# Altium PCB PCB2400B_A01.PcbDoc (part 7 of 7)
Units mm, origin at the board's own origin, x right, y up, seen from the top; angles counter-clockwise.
Board outline 115 x 60 mm, 6 copper layers (Top Layer, Signal Layer 2, Signal Layer 3, Signal Layer 4, Signal Layer 5, Bottom Layer), stack 1.555 mm thick; 382 components, 308 nets, 1384 pads, 1152 vias.
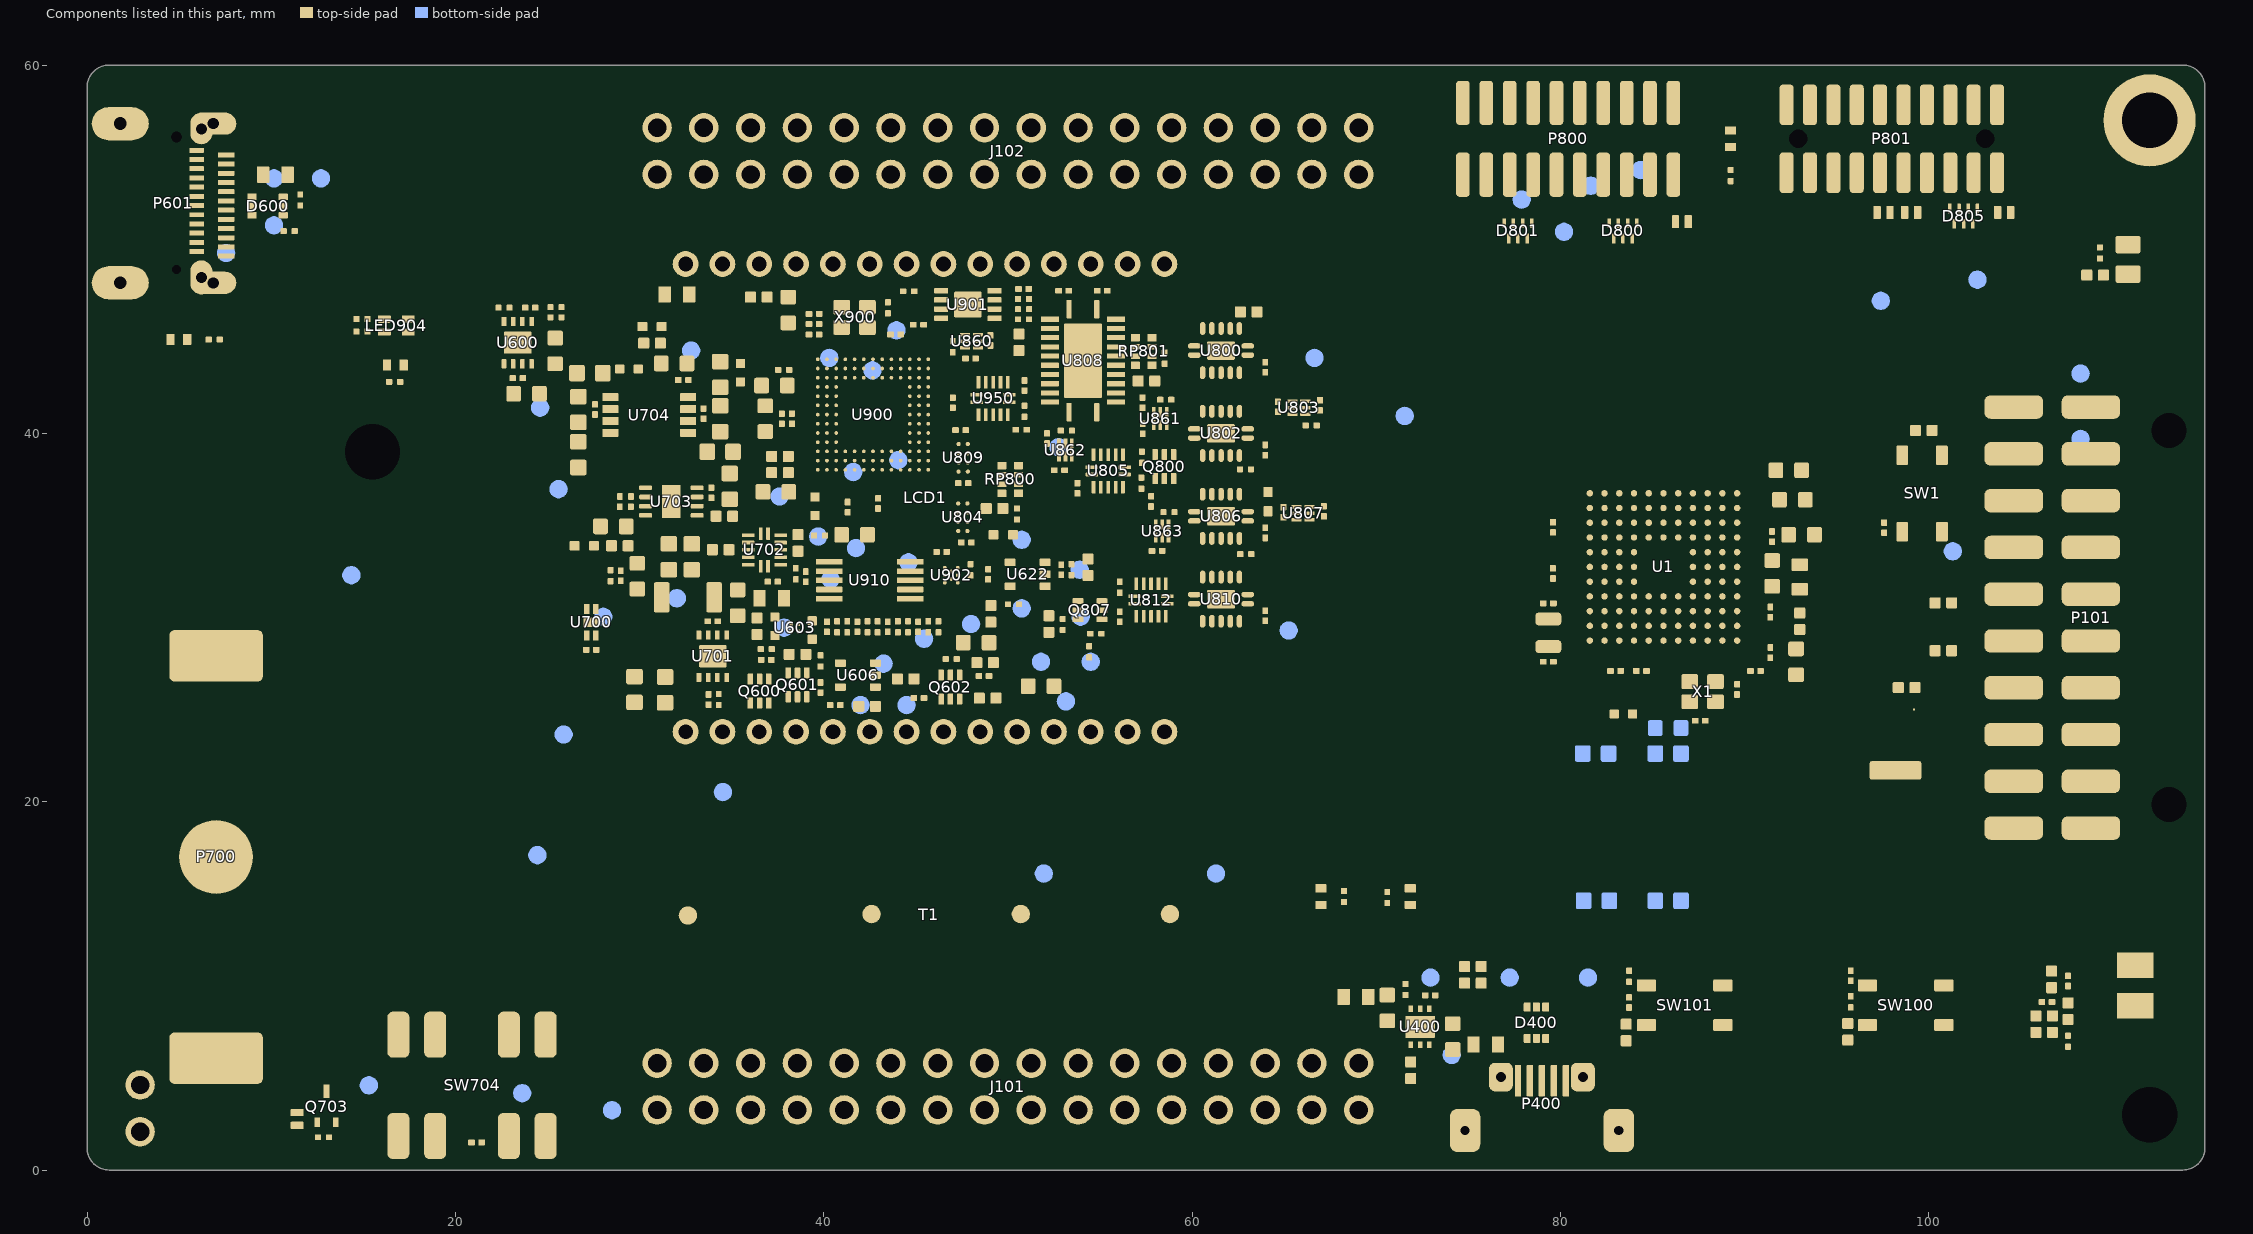
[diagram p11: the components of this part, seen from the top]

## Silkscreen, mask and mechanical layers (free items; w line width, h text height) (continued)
Mechanical 98:
  circle w0.013: c106.206,55.506 r1.25
  circle w0.013: c64.693,-0.477 r2
  circle w0.013: c35.293,-0.477 r2
  circle w0.013: c64.693,60.323 r2
  circle w0.013: c67.037,17.813 r1.25
  circle w0.013: c35.293,60.323 r2
  circle w0.013: c27.063,15.719 r1.25
  circle w0.013: c5.676,38.649 r1.25
  circle w0.013: c103.355,13.007 r1.25
  circle w0.013: c13.685,1.607 r1.25
  circle w0.013: c15.502,38.991 r1.55
  circle w0.013: c15.502,38.991 r1.55
  circle w0.013: c112.002,2.991 r1.55
  circle w0.013: c112.002,56.992 r1.55
  lines w0.013: 67.293,55.346 67.293,65.323 ; 30.293,-5.477 69.693,-5.477 69.693,4.523 30.293,4.523 30.293,-5.477 ; 30.293,55.323 69.693,55.323 69.693,65.323 30.293,65.323 30.293,55.323
  text "Pressure" at 47.486,59.887 h1.52
  text "Hole" at 111.367,56.712 h0.76
  text "Pressure / (NM)" at 105.398,54.934 h0.51
  text "Pressure" at 4.814,38.551 h0.51
  text "Guide / hole" at 14.72,38.424 h0.76
  text "Guide / hole" at 14.72,38.424 h0.76
  text "Pressure / (NM)" at 66.155,17.342 h0.51
  text "Pressure / (NM)" at 25.642,15.183 h0.51
  text "Pressure" at 102.477,12.77 h0.51
  text "Guide / hole" at 111.113,2.356 h0.76
  text "Pressure / (NM)" at 12.815,1.086 h0.51
  text "Pressure" at 47.486,-1.327 h1.52
Mechanical 99:
  drawing of 609 lines, arcs and shapes, not listed
  text "Hole" at 111.365,56.722 h0.76
  text "P1-1" at 15.48,54.74 h0.51
  text "TPJ814" at 83.577,54.105 h0.51
  text "TPJ613" at 11.949,53.699 h0.51
  text "TPJ612" at 9.384,53.623 h0.51
  text "TPJ415" at 106.412,53.572 h0.38
  text "P2-1" at 87.031,53.547 h0.51
  text "P2-7" at 93.127,53.547 h0.51
  text "P2-3" at 89.063,53.521 h0.51
  text "TPJ412" at 103.897,53.521 h0.38
  text "P1-2" at 18.02,53.445 h0.51
  text "TPJ812" at 80.859,53.267 h0.51
  text "TPJ811" at 77.125,52.48 h0.51
  text "P1-3" at 15.454,52.2 h0.51
  text "TPJ414" at 104.862,51.845 h0.38
  text "TPJ413" at 102.805,51.819 h0.38
  text "P2-6" at 92.111,51.769 h0.51
  text "P2-2" at 88.047,51.743 h0.51
  text "P2-4" at 90.079,51.743 h0.51
  text "TPJ813" at 84.618,51.515 h0.51
  text "TPJ611" at 9.384,51.108 h0.51
  text "P1-4" at 17.994,50.905 h0.51
  text "TPJ820" at 79.386,50.727 h0.51
  text "P1-5" at 15.48,49.635 h0.51
  text "TPJ614" at 6.767,49.61 h0.51
  text "P1-6" at 17.994,48.365 h0.51
  text "TPJ817" at 101.865,48.136 h0.51
  text "TPJ507" at 72.807,47.857 h0.38
  text "TPJ503" at 74.814,47.857 h0.38
  text "TPJ505" at 76.846,47.857 h0.38
  text "TPJ606" at 96.607,46.993 h0.51
  text "P1-8" at 18.02,45.825 h0.51
  text "TPJ500" at 70.826,45.673 h0.38
  text "TPJ506" at 72.833,45.647 h0.38
  text "TPJ502" at 74.839,45.647 h0.38
  text "TPJ504" at 76.846,45.647 h0.38
  text "TPJ908" at 43.14,45.419 h0.51
  text "Support / pin" at 21.703,44.784 h1.02
  text "Support / pin" at 85.711,44.657 h1.02
  text "TPJ607" at 65.848,43.895 h0.51
  text "TPJ909" at 41.845,43.234 h0.51
  text "TPJ650" at 107.478,43.031 h0.51
  text "TPJ501" at 72.833,42.929 h0.38
  text "TPJ807" at 92.67,42.091 h0.51
  text "TPJ902" at 23.836,41.202 h0.51
  text "TPJ905" at 53.884,40.923 h0.51
  text "TPJ818" at 70.75,40.77 h0.51
  text "TPJ651" at 107.453,39.475 h0.51
  text "TPJ609" at 85.355,39.323 h0.51
  text "TPJ956" at 51.954,39.043 h0.51
  text "Guide / hole" at 14.718,38.434 h0.76
  text "Guide / hole" at 14.718,38.434 h0.76
  text "TPJ901" at 43.293,38.357 h0.51
  text "TPJ900" at 40.778,37.697 h0.51
  text "TPJ930" at 35.444,36.833 h0.51
  text "TPJ931" at 38.238,36.833 h0.51
  text "Cutout" at -9.057,36.275 h1.52
  text "TPJ604" at 9.612,34.192 h0.51
  text "TPJ912" at 49.947,34.065 h0.51
  text "TPJ960" at 53.122,32.414 h0.51
  text "TPJ600" at 13.575,32.084 h0.51
  text "TPJ603" at 9.612,31.576 h0.51
  text "TPJ913" at 49.947,30.306 h0.51
  text "TPJ961" at 53.173,29.874 h0.51
  text "TPJ910" at 47.204,29.442 h0.51
  text "TPJ601" at 8.698,29.086 h0.51
  text "TPJ602" at 11.238,29.061 h0.51
  text "TPJ911" at 44.69,28.655 h0.51
  text "TPJ959" at 53.707,27.41 h0.51
  text "TPJ957" at 50.989,27.385 h0.51
  text "TPJ954" at 42.505,27.283 h0.51
  text "TPJ616" at 14.895,25.734 h0.51
  text "TPJ615" at 11.263,25.708 h0.51
  text "TPJ958" at 52.386,25.251 h0.51
  text "TPJ953" at 41.21,25.048 h0.51
  text "TPJ955" at 43.724,25.022 h0.51
  text "TPJ952" at 46.214,25.022 h0.51
  text "TPJ608" at 33.742,20.323 h0.51
  text "TPJ950" at 23.684,16.894 h0.51
  text "TPJ653" at 51.167,15.878 h0.51
  text "TPJ652" at 60.539,15.878 h0.51
  text "TPJ804" at 93.407,11.662 h0.51
  text "TPJ803" at 96.023,11.129 h0.51
  text "TPJ404" at 72.198,10.29 h0.51
  text "TPJ403" at 76.49,10.265 h0.51
  text "TPJ402" at 80.732,10.214 h0.51
  text "Cutout" at 114.413,9.986 h1.52
  text "Support / pin" at 103.745,9.859 h1.02
  text "Support / pin" at 21.703,9.732 h1.02
  text "TPJ808" at 92.467,9.224 h0.51
  text "TPJ801" at 95.718,8.462 h0.51
  text "TPJ802" at 92.467,6.684 h0.51
  text "TPJ405" at 73.315,6.049 h0.51
  text "TPJ810" at 94.931,5.845 h0.51
  text "Guide / hole" at 111.111,2.366 h0.76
